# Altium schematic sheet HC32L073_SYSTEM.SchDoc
size A4; CompanyName: 广州立功科技股份有限公司; DocumentNumber: 3; SheetNumber: 3; SheetTotal: 12; PageSetup: Record=PageOptions|CenterHorizontal=True|CenterVertical=True|PrintScale=1.00|XCorrection=1.00|YCorrection=1.00|PrintKind=0|BorderSize=5000000|LeftOffset=0|BottomOffset=0|Orientation=2|PaperLength=1000|PaperWidth=1000|Scale=100|PaperSource=7|PrintQuality=600|MediaType=1|DitherType=10|PaperKind=A4|PrintScaleMode=1; DesignDate: 2020-07-08; SheetName: HC32L073_SYSTEM; SheetVersion: Rev.B; SheetDescription: HC32L073最小系统子图
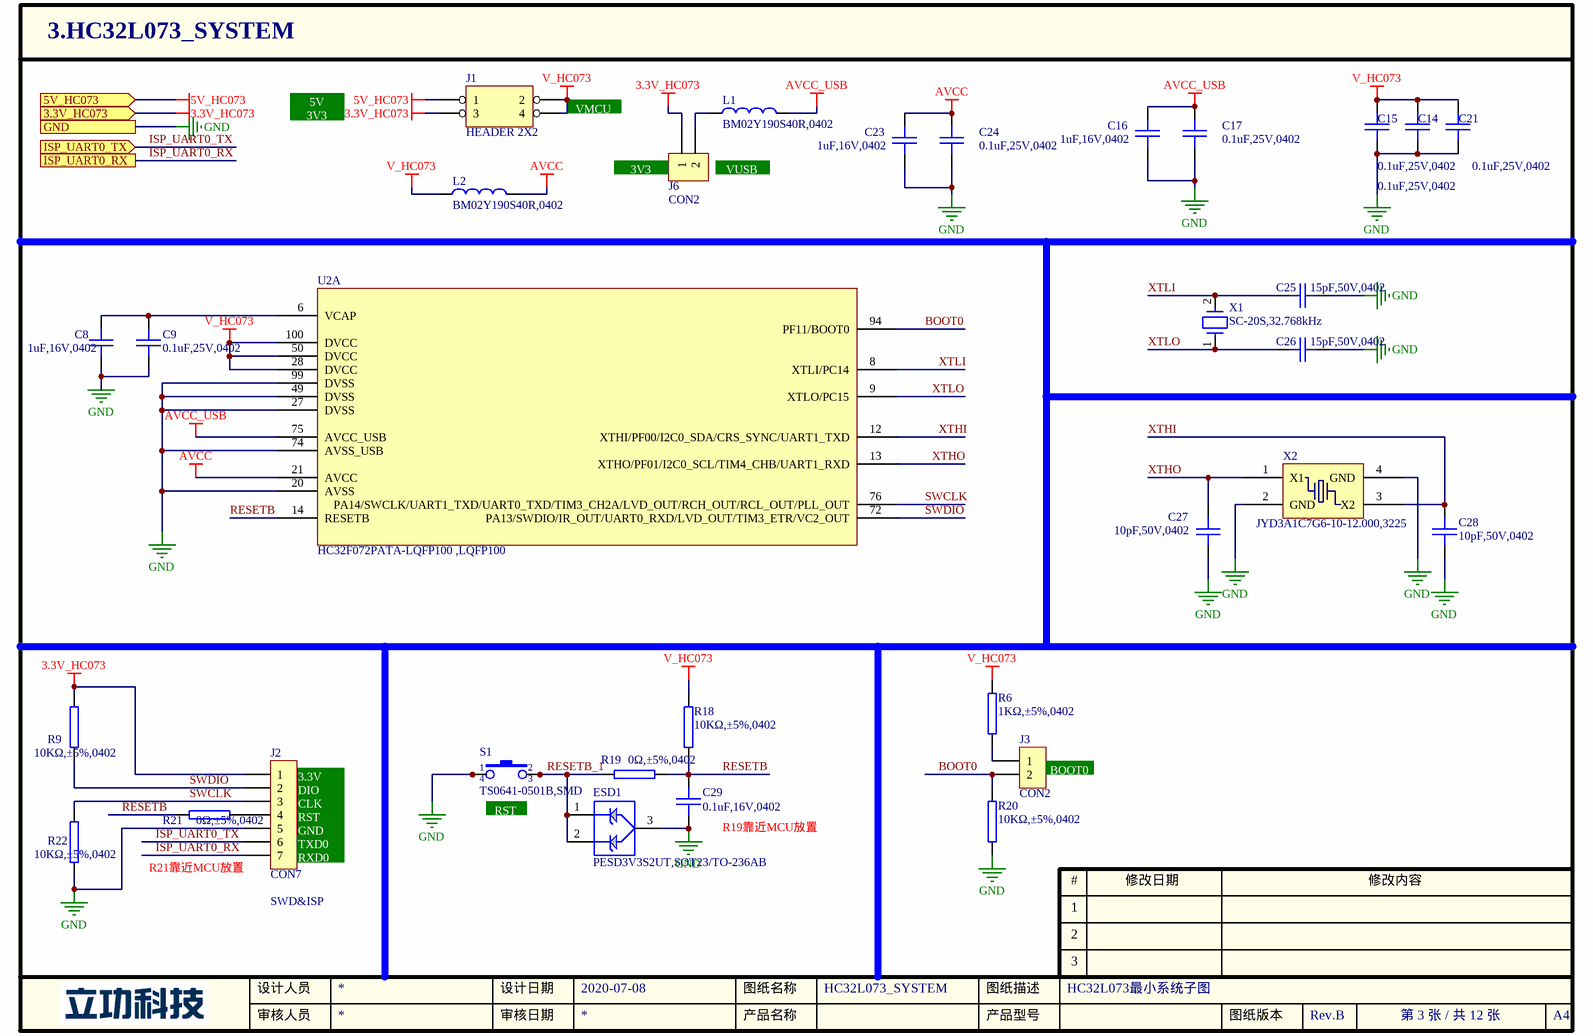
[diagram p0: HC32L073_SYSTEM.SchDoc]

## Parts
C8  1uF,16V,0402  [0402C]
C9  0.1uF,25V,0402  [0402C]
C14  0.1uF,25V,0402  [0402C]
C15  0.1uF,25V,0402  [0402C]
C16  1uF,16V,0402  [0402C]
C17  0.1uF,25V,0402  [0402C]
C21  0.1uF,25V,0402  [0402C]
C23  1uF,16V,0402  [0402C]
C24  0.1uF,25V,0402  [0402C]
C25  15pF,50V,0402  [0402C]
C26  15pF,50V,0402  [0402C]
C27  10pF,50V,0402  [0402C]
C28  10pF,50V,0402  [0402C]
C29  0.1uF,16V,0402  [0402C]
ESD1  PESD3V3S2UT,SOT23/TO-236AB  [SOT-23]
J1  HEADER 2X2  [IDC-4-2.54]
J2  CON7  [SIP-7-2.54]
J3  CON2  [SIP-2-2.54]
J6  CON2  [SIP-2-2.54]
L1  BM02Y190S40R,0402  [0402L]
L2  BM02Y190S40R,0402  [0402L]
R6  1KΩ,±5%,0402  [0402R]
R9  10KΩ,±5%,0402  [0402R]
R18  10KΩ,±5%,0402  [0402R]
R19  0Ω,±5%,0402  [0402R]
R20  10KΩ,±5%,0402  [0402R]
R21  0Ω,±5%,0402  [0402R]
R22  10KΩ,±5%,0402  [0402R]
S1  TS0641-0501B,SMD  [KEY-6S]
U2  HC32F072PATA-LQFP100 / ,LQFP100  [QFP50P1600X1600X120-100N]  (part A of 3)
X1  SC-20S,32.768kHz  [XTAL205X120X60-2N]
X2  JYD3A1C7G6-10-12.000,3225  [OSCCC250X320X80-4N]

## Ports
3.3V_HC073 (in), 5V_HC073 (in), GND, ISP_UART0_RX, ISP_UART0_TX (in)

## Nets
3.3V_HC073: J1.3 J2.1 J6.1 R9.2 ; port 3.3V_HC073
5V_HC073: J1.1 ; port 5V_HC073
AVCC: C23.1 C24.1 L2.2 U2.21(AVCC)
AVCC_USB: C16.1 C17.1 L1.2 U2.75(AVCC_USB)
GND: C8.2 C9.2 C14.2 C15.2 C16.2 C17.2 C21.2 C23.2 C24.2 C25.2 C26.2 C27.1 C28.1 C29.2 ESD1.3 J2.5 R20.2 R22.1 S1.1 S1.4 U2.20(AVSS) U2.27(DVSS) U2.49(DVSS) U2.74(AVSS_USB) U2.99(DVSS) X2.2(GND) X2.4(GND) ; port GND
V_HC073: C14.1 C15.1 C21.1 J1.2 J1.4 L2.1 R6.2 R18.2 U2.28(DVCC) U2.50(DVCC) U2.100(DVCC)
BOOT0: J3.2 R20.1 U2.94(PF11/BOOT0)
ISP_UART0_RX: J2.7 ; port ISP_UART0_RX
ISP_UART0_TX: J2.6 ; port ISP_UART0_TX
RESETB: C29.1 R18.1 R19.1 R21.2 U2.14(RESETB)
RESETB_1: ESD1.1 ESD1.2 R19.2 S1.2 S1.3
SWCLK: J2.3 R22.2 U2.76(PA14/SWCLK/UART1_TXD/UART0_TXD/TIM3_CH2A/LVD_OUT/RCH_OUT/RCL_OUT/PLL_OUT)
SWDIO: J2.2 R9.1 U2.72(PA13/SWDIO/IR_OUT/UART0_RXD/LVD_OUT/TIM3_ETR/VC2_OUT)
XTHI: C28.2 U2.12(XTHI/PF00/I2C0_SDA/CRS_SYNC/UART1_TXD) X2.3(X2)
XTHO: C27.2 U2.13(XTHO/PF01/I2C0_SCL/TIM4_CHB/UART1_RXD) X2.1(X1)
XTLI: C25.1 U2.8(XTLI/PC14) X1.2
XTLO: C26.1 U2.9(XTLO/PC15) X1.1
NetC8_1: C8.1 C9.1 U2.6(VCAP)
NetJ2_4: J2.4 R21.1
NetJ3_1: J3.1 R6.1
NetJ6_2: J6.2 L1.1

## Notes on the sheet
- 5V
- 3V3
- (near J1) VMCU
- (near J6) 3V3
- (near J6) VUSB
- (near J2) 3.3V
- (near J2) DIO
- (near J3) BOOT0
- (near J2) CLK
- (near J2) RST
- (near J2) GND
- (near J2) TXD0
- (near S1) RST
- (near C29) R19靠近MCU放置
- R21靠近MCU放置
- (near J2) SWD&ISP
- (near J2) RXD0

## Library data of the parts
C8 C16 C23 = 02.01.00333: GRM155R61C105KA12D,0402,MURATA,1uF,X5R,±10%,16V,; 旧物料代码: 1.02.17.0092; 名称: 电容; 封装: 0402; 贴片和直插: SMT; PCB备注: 无数据手册，依据采购部提供的信息添加的封装。; 器件优选方案: 不推荐使用
C9 C14 C15 C17 C21 C24 = 02.01.00276: GRM155R61E104KA87D,0402,MURATA,0.1uF,X5R,±10%,25V,; 旧物料代码: 1.02.17.0020; 名称: 电容; 封装: 0402; 贴片和直插: SMT; 器件优选方案: 通用物料
C25 C26 = 02.01.00262: GRM1555C1H150JA01D,0402,MURATA,15pF,C0G,±5%,50V,; 旧物料代码: 1.02.17.0005; 名称: 电容; 封装: 0402; 贴片和直插: SMT; 器件优选方案: 通用物料
C27 C28 = 02.01.00265: GRM1555C1H100JA01D,0402,MURATA,10pF,COG,±0.5PF,50V,; 旧物料代码: 1.02.17.0008; 名称: 电容; 封装: 0402; 贴片和直插: SMT; 器件优选方案: 通用物料
C29 = 02.01.00263: GRM155R71C104KA88D,0402,MURATA,0.1uF,X7R,±10%,16V,; 旧物料代码: 1.02.17.0006; 名称: 电容; 封装: 0402; 贴片和直插: SMT; 器件优选方案: 通用物料
ESD1 = 09.04.00156: PESD3V3S2UT,SOT23/TO-236AB,NEXPERIA,; 旧物料代码: 1.05.10.0361; 名称: 二极管; 贴片和直插: SMT; 器件优选方案: 通用物料
J2 = CON7: Connector
J3 J6 = CON2: Connector
L1 L2 = 03.03.00024: BM02Y190S40R,0402,GAUSSTEK,40Ω,±25%,DCR,Max0.25Ω,0.5A,; 名称: 磁珠; 封装: 0402; 贴片和直插: SMT; 器件优选方案: 通用物料; 旧物料代码: 1.03.03.0022
R6 = 01.01.00007: RTT02102JTH,0402,RALEC,1KΩ,±5%,1/16W,; 名称: 电阻; 封装: 0402; 贴片和直插: SMT; 器件优选方案: 通用物料; 旧物料代码: 1.01.17.0022
R9 R18 R22 = 01.01.00001: RTT02103JTH,0402,RALEC,10KΩ,±5%,1/16W; 旧物料代码: 1.01.17.0006; 名称: 电阻; 封装: 0402; 贴片和直插: SMT; 器件优选方案: 通用物料
R19 R21 = 01.01.00004: RTT02000JTH,0402,RALEC,0Ω,±5%,1/16W,; 旧物料代码: 1.01.17.0004; 名称: 电阻; 封装: 0402; 贴片和直插: SMT; 器件优选方案: 通用物料
R20 = 01.01.00001: RTT02103JTH,0402,RALEC,10KΩ,±5%,1/16W; 名称: 电阻; 封装: 0402; 贴片和直插: SMT; 器件优选方案: 通用物料; 旧物料代码: 1.01.17.0006
S1 = 17.01.00005: TS0641-0501B,SMD,DAILYLON,黑色,卷带装,6*6*5.0mm,; 名称: 轻触开关; 贴片和直插: SMT; 器件优选方案: 通用物料; 旧物料代码: 1.09.01.0003
U2 = 08.20.00249: HC32F072PATA-LQFP100 / ,LQFP100,华大HDSC; 名称: 集成电路; 贴片和直插: SMT; PCB备注: 200929hcj; 器件优选方案: 待导入物料
X1 = 12.02.00196: SC-20S,32.768kHz,12.5pF,±20ppm,SMD2012,SII; 名称: 晶体; 封装: SMT; PCB备注: 180227ZW; 器件优选方案: 不推荐使用; 旧物料代码: 1.07.01.0071
X2 = 12.02.00162: JYD3A1C7G6-10-12.000,3225,JYEG,12MHz,±10ppm,10pF,-40~85℃,; 旧物料代码: 1.07.01.0032; 名称: 晶体; 封装: SMT; PCB备注: 151229lmd171128ZW; 器件优选方案: 通用物料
